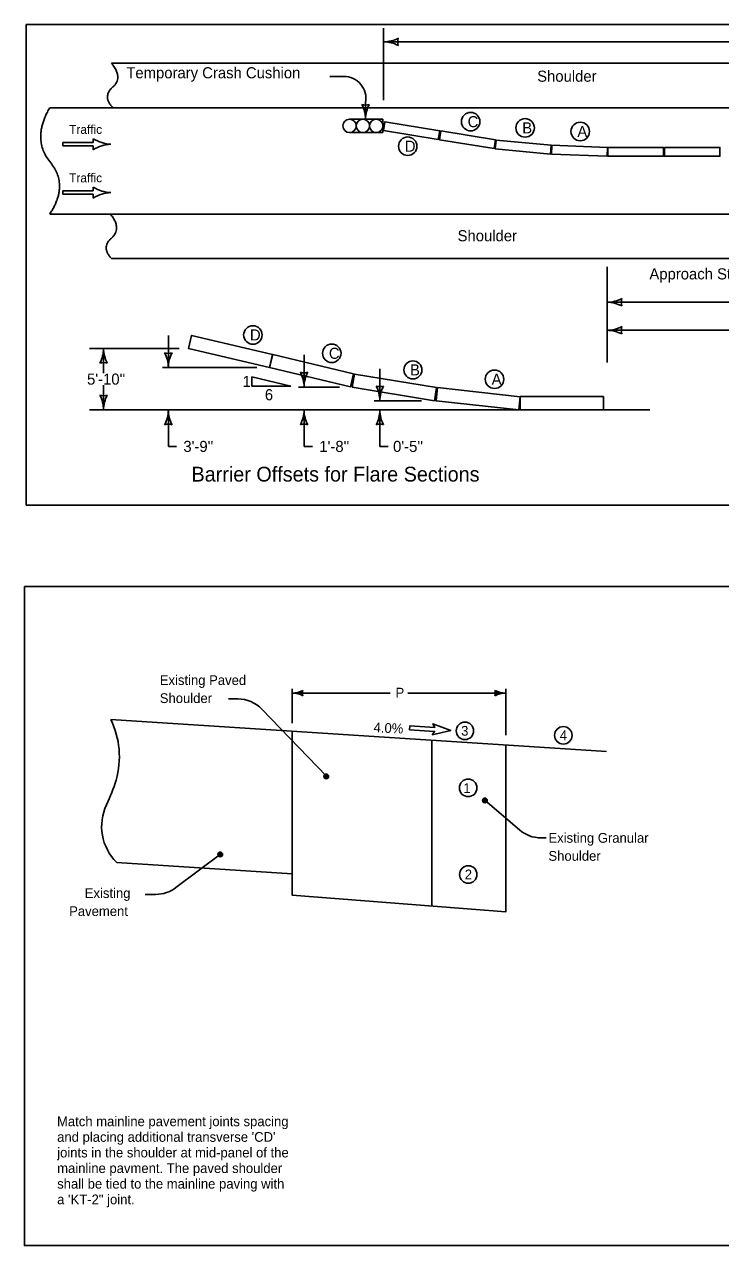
# Model space of a CAD drawing. Extents: x 8045 to 81668, y 6217 to 16762.
# Drawn here: x 8045 to 8986, y 10467 to 12118 of the extents above; entities that cross this region are included whole.
import ezdxf

# ---------------------------------------------------------------- set-up
doc = ezdxf.new("R2010")
doc.units = 0
for name, color, linetype in [('dsnNonPlotable', 7, 'Continuous'), ('dsnStdBlock', 7, 'Continuous'), ('dsnStdBlockModified', 7, 'Continuous'), ('dsnStdBorder', 7, 'Continuous'), ('dsnStdLineWork', 7, 'Continuous'), ('dsnStdNameDate', 7, 'Continuous'), ('Level 5', 7, 'Continuous')]:
    doc.layers.add(name, color=color, linetype=linetype)

msp = doc.modelspace()

# ---------------------------------------------------------------- linework, layer by layer
at = {"layer": 'dsnNonPlotable'}
for p, q in [((8530, 12113.1), (8530, 12015.6)), ((8530, 12094.5), (9408.5, 12094.5)), ((8162.3, 12065.5), (9290.8, 12065.5)), ((8476.2, 12047.8), (8457.5, 12047.8)), ((8078.7, 12005.5), (9320.8, 12005.5)), ((8505.7, 12012.4), (8505.7, 11989.9)), ((8484.1, 11989.9), (8529.1, 11989.9)), ((8529.1, 11989.9), (8529.1, 11971.9)), ((8529.1, 11971.9), (8484.1, 11971.9)), ((8527.9, 11977.6), (8529.2, 11977.3)), ((8529.7, 11973.9), (8529.7, 11973.9)), ((8137.6, 11958.3), (8096.3, 11958.3)), ((8096.3, 11958.3), (8096.3, 11953.8)), ((8137.6, 11963.6), (8137.6, 11958.3)), ((8161.5, 11956.1), (8161.5, 11956.1)), ((8096.3, 11953.8), (8137.6, 11953.8)), ((8137.6, 11953.8), (8137.6, 11948.6)), ((8137.6, 11892.9), (8096.3, 11892.9)), ((8096.3, 11892.9), (8096.3, 11888.4)), ((8137.6, 11898.1), (8137.6, 11892.9)), ((8161.5, 11890.6), (8161.5, 11890.6)), ((8096.3, 11888.4), (8137.6, 11888.4)), ((8137.6, 11888.4), (8137.6, 11883.1)), ((8078.7, 11861.5), (9320.8, 11861.5)), ((8162.3, 11801.5), (9290.8, 11801.5)), ((8832.1, 11790.2), (8832.1, 11661.1)), ((8832.1, 11742.4), (9058.2, 11742.4)), ((8239.1, 11697.6), (8239.1, 11654.1)), ((8832.1, 11704.5), (9422.9, 11704.5)), ((8253.6, 11680.1), (8132.4, 11680.1)), ((8151.5, 11680.1), (8151.5, 11646.6)), ((8422.6, 11671.2), (8422.6, 11627.7)), ((8358.5, 11654.1), (8231.3, 11654.1)), ((8525, 11652.6), (8525, 11609.1)), ((8151.5, 11630.3), (8151.5, 11596.8)), ((8470.4, 11627.7), (8414.9, 11627.7)), ((8581.3, 11609.1), (8517.2, 11609.1)), ((8889.8, 11596.8), (8132.4, 11596.8)), ((8239.1, 11596.8), (8239.1, 11547.5)), ((8422.6, 11596.8), (8422.6, 11547.5)), ((8525, 11596.8), (8525, 11569.8)), ((8525, 11569.8), (8525, 11547.5)), ((8239.1, 11547.5), (8250.2, 11547.5)), ((8422.6, 11547.5), (8433.8, 11547.5)), ((8525, 11547.5), (8536.1, 11547.5))]:
    msp.add_line(p, q, dxfattribs=at)
for points in [[(8605.9, 11974.3), (8531.9, 11986.5), (8530, 11974.6), (8604, 11962.5)], [(8681.4, 11961.9), (8607.4, 11974.1), (8605.5, 11962.2), (8679.5, 11950.1)], [(8756.8, 11954.7), (8682.2, 11961.8), (8681, 11949.9), (8755.7, 11942.8)], [(8832.6, 11951.8), (8757.7, 11954.8), (8757.2, 11942.8), (8832.1, 11939.8)], [(8833.3, 11951.8), (8908.3, 11951.8), (8908.3, 11939.8), (8833.3, 11939.8)], [(8909.8, 11951.8), (8984.8, 11951.8), (8984.8, 11939.8), (8909.8, 11939.8)], [(8379.9, 11671.7), (8270.4, 11697.6), (8266.2, 11680.1), (8375.7, 11654.2)], [(8489.6, 11645.7), (8380.2, 11671.6), (8376, 11654.1), (8485.5, 11628.2)], [(8601.7, 11627), (8490.7, 11645.4), (8487.8, 11627.7), (8598.8, 11609.2)], [(8714.8, 11614.7), (8603, 11627), (8601, 11609.1), (8712.8, 11596.8)], [(8827.3, 11614.8), (8714.8, 11614.8), (8714.8, 11596.8), (8827.3, 11596.8)]]:
    msp.add_lwpolyline(points, close=True, dxfattribs=at)
for centre, radius in [((8484.1, 11980.9), 9), ((8484.1, 11980.9), 9), ((8502.1, 11980.9), 9), ((8502.1, 11980.9), 9), ((8520.1, 11980.9), 9), ((8520.1, 11980.9), 9), ((8647.7, 11986.6), 12.5), ((8721.4, 11978.2), 12.5), ((8795.9, 11973.3), 12.5), ((8562.7, 11953.4), 12.5), ((8353.4, 11698.2), 12.5), ((8460, 11673.4), 12.5), ((8569.7, 11651), 12.2), ((8680, 11638.3), 12.5)]:
    msp.add_circle(centre, radius, dxfattribs=at)
for centre, radius, start, end in [((8530, 12137), 42.5, 270, 298.0725), ((8530, 12052), 42.5, 61.9275, 90), ((8565.6, 12094.5), 16.4, 162.2666, 197.7334), ((8476.2, 12017.8), 30, 349.6463, 90), ((8505.7, 12025.5), 16.4, 252.2666, 287.7333), ((8463.2, 11989.9), 42.5, 360, 28.0725), ((8548.2, 11989.9), 42.5, 151.9275, 180), ((8163.5, 12004.4), 48.4, 237.618, 267.648), ((8163.5, 11907.8), 48.4, 92.352, 122.382), ((8163.5, 11939), 48.4, 237.618, 267.648), ((8163.5, 11842.3), 48.4, 92.352, 122.382), ((8832.1, 11784.9), 42.5, 270, 298.0725), ((8832.1, 11699.9), 42.5, 61.9275, 90), ((8867.8, 11742.4), 16.4, 162.2666, 197.7334), ((8832.1, 11747), 42.5, 270, 298.0725), ((8867.8, 11704.5), 16.4, 162.2666, 197.7334), ((8832.1, 11662), 42.5, 61.9275, 90), ((8109, 11680.1), 42.5, 331.9275, 0), ((8194, 11680.1), 42.5, 180, 208.0725), ((8239.1, 11689.7), 16.4, 252.2666, 287.7334), ((8196.6, 11654.1), 42.5, 0, 28.0725), ((8281.6, 11654.1), 42.5, 151.9275, 180), ((8151.5, 11644.4), 16.4, 72.2666, 107.7334), ((8422.6, 11663.3), 16.4, 252.2666, 287.7334), ((8380.1, 11627.7), 42.5, 0, 28.0725), ((8465.1, 11627.7), 42.5, 151.9275, 180), ((8525, 11644.7), 16.4, 252.2666, 287.7334), ((8482.5, 11609.1), 42.5, 0, 28.0725), ((8567.5, 11609.1), 42.5, 151.9275, 180), ((8151.5, 11632.4), 16.4, 252.2666, 287.7334), ((8109, 11596.8), 42.5, 0, 28.0725), ((8194, 11596.8), 42.5, 151.9275, 180), ((8196.6, 11596.8), 42.5, 331.9275, 0), ((8281.6, 11596.8), 42.5, 180, 208.0725), ((8380.1, 11596.8), 42.5, 331.9275, 0), ((8465.1, 11596.8), 42.5, 180, 208.0725), ((8482.5, 11596.8), 42.5, 331.9275, 0), ((8567.5, 11596.8), 42.5, 180, 208.0725), ((8239.1, 11561.2), 16.4, 72.2666, 107.7334), ((8422.6, 11561.2), 16.4, 72.2666, 107.7334), ((8525, 11561.2), 16.4, 72.2666, 107.7334)]:
    msp.add_arc(centre, radius, start, end, dxfattribs=at)
for points in [[(8162.3, 12065.5), (8178.4, 12046.2), (8149.5, 12020.6), (8164, 12005.5)], [(8078.7, 12005.5), (8054.1, 11962.9), (8104.9, 11900.7), (8078.7, 11861.5)], [(8160.7, 11861.5), (8176.8, 11842.1), (8147.9, 11816.5), (8162.3, 11801.5)]]:
    msp.add_open_spline(points, degree=2, dxfattribs=at)
at = {"layer": 'dsnStdBlock'}
msp.add_line((8047, 12118.1), (8047, 12118.1), dxfattribs=at)
at = {"layer": 'dsnStdBlockModified'}
for p, q in [((8047, 12118.1), (11152, 12118.1)), ((8047, 11468.1), (8047, 12118.1))]:
    msp.add_line(p, q, dxfattribs=at)
at = {"layer": 'dsnStdBorder'}
msp.add_line((11152, 11468.1), (8047, 11468.1), dxfattribs=at)
at = {"layer": 'dsnStdLineWork'}
for p, q in [((8406.6, 11173.2), (8406.6, 11219.5)), ((8406.6, 11213.9), (8420.4, 11213.9)), ((8406.6, 11213.9), (8538.9, 11213.9)), ((8562.8, 11213.9), (8695.1, 11213.9)), ((8695.1, 11213.9), (8681.2, 11213.9)), ((8695.1, 11157.2), (8695.1, 11219.5)), ((8320.4, 11206.1), (8333.1, 11206.1)), ((8365.6, 11192.3), (8452.8, 11101.5)), ((8161.2, 11178.2), (8831.5, 11134.8)), ((8595.3, 10925.9), (8595.3, 11150.1)), ((8713.6, 11029.1), (8667.3, 11068.8)), ((8749.8, 11018.2), (8742.9, 11018.2)), ((8169.4, 10984.9), (8406.6, 10969.5)), ((8249.4, 10951.1), (8309.4, 10996.1)), ((8221.9, 10941.7), (8207.9, 10941.7))]:
    msp.add_line(p, q, dxfattribs=at)
for points in [[(8420.1, 11211.3), (8419.6, 11213.9), (8420.1, 11216.5), (8417.1, 11215), (8412.1, 11213.9), (8417.4, 11212.7), (8419.7, 11211.7), (8419.1, 11213.9), (8419.3, 11215.6), (8417.3, 11214.6), (8414.6, 11213.9), (8417.5, 11213.1), (8419, 11212.6), (8418.7, 11214.8), (8416.7, 11213.9), (8418.3, 11213.4), (8418.3, 11214.2), (8417.6, 11213.9)], [(8681.5, 11216.5), (8682, 11213.9), (8681.5, 11211.3), (8684.6, 11212.8), (8689.5, 11213.9), (8684.2, 11215.1), (8681.9, 11216.1), (8682.5, 11213.9), (8682.3, 11212.2), (8684.3, 11213.2), (8687, 11213.9), (8684.1, 11214.7), (8682.6, 11215.3), (8682.9, 11213.1), (8684.9, 11213.9), (8683.3, 11214.4), (8683.3, 11213.6), (8684, 11213.9)], [(8406.6, 11162.6), (8406.6, 10940.7), (8695.1, 10918.1), (8695.1, 11143.7)], [(8454.8, 11103.1), (8453.7, 11103.5), (8452.1, 11104.4), (8450.7, 11103.4), (8449.9, 11102.2), (8449.6, 11100.5), (8450.8, 11099.5), (8452.2, 11098.5), (8453.7, 11098.8), (8454.8, 11099.7), (8455.4, 11101.7), (8454.6, 11102.7), (8453.2, 11103.5), (8451.4, 11103.7), (8450.4, 11102.6), (8450.2, 11101), (8451.2, 11099.8), (8452.6, 11098.9), (8453.4, 11099.3), (8454.4, 11099.9), (8454.9, 11101.4), (8454, 11102.2), (8452.8, 11103.1), (8451.6, 11103.2), (8451, 11101.9), (8451.1, 11100.6), (8452.1, 11099.6), (8452.9, 11099.9), (8453.8, 11100.1), (8454.1, 11101.4), (8453.5, 11102.3), (8452.5, 11102.6), (8451.8, 11101.9), (8451.6, 11101.1), (8452.1, 11100.2), (8452.7, 11100.2), (8453.2, 11100.4), (8453.5, 11101.3), (8453.1, 11101.9), (8452.4, 11102.1), (8452.1, 11101.6), (8452.2, 11101), (8452.6, 11100.6), (8453, 11100.9), (8452.8, 11101.5)], [(8669.2, 11070.7), (8668.1, 11071.2), (8666.6, 11072), (8665.2, 11071), (8664.3, 11069.8), (8664.1, 11068.1), (8665.3, 11067.1), (8666.6, 11066.1), (8668.1, 11066.4), (8669.2, 11067.3), (8669.8, 11069.3), (8669.1, 11070.3), (8667.6, 11071.1), (8665.9, 11071.4), (8664.8, 11070.2), (8664.7, 11068.6), (8665.6, 11067.4), (8667, 11066.5), (8667.9, 11067), (8668.9, 11067.5), (8669.3, 11069), (8668.4, 11069.9), (8667.3, 11070.7), (8666, 11070.8), (8665.4, 11069.5), (8665.6, 11068.2), (8666.5, 11067.2), (8667.3, 11067.5), (8668.2, 11067.8), (8668.5, 11069), (8668, 11069.9), (8667, 11070.2), (8666.2, 11069.5), (8666, 11068.7), (8666.5, 11067.8), (8667.1, 11067.8), (8667.7, 11068), (8667.9, 11068.9), (8667.6, 11069.5), (8666.9, 11069.7), (8666.5, 11069.2), (8666.6, 11068.6), (8667.1, 11068.2), (8667.4, 11068.5), (8667.2, 11069.1)], [(8311.4, 10997.7), (8310.3, 10998.1), (8308.8, 10998.9), (8307.4, 10998), (8306.5, 10996.8), (8306.3, 10995.1), (8307.5, 10994), (8308.9, 10993), (8310.4, 10993.4), (8311.4, 10994.3), (8312, 10996.3), (8311.3, 10997.2), (8309.8, 10998.1), (8308.1, 10998.3), (8307, 10997.2), (8306.9, 10995.5), (8307.8, 10994.4), (8309.2, 10993.4), (8310.1, 10993.9), (8311.1, 10994.5), (8311.5, 10996), (8310.6, 10996.8), (8309.5, 10997.6), (8308.3, 10997.8), (8307.6, 10996.5), (8307.8, 10995.2), (8308.8, 10994.1), (8309.5, 10994.4), (8310.4, 10994.7), (8310.7, 10996), (8310.2, 10996.9), (8309.2, 10997.2), (8308.4, 10996.5), (8308.3, 10995.6), (8308.7, 10994.8), (8309.3, 10994.8), (8309.9, 10995), (8310.2, 10995.9), (8309.8, 10996.5), (8309.1, 10996.6), (8308.8, 10996.2), (8308.8, 10995.6), (8309.3, 10995.1), (8309.6, 10995.5), (8309.4, 10996.1)]]:
    msp.add_lwpolyline(points, dxfattribs=at)
msp.add_lwpolyline([(8595.8, 11157.3), (8620.8, 11163.5), (8596.7, 11172.5), (8599.3, 11167.3), (8565.5, 11169.5), (8565.2, 11164.3), (8599, 11162.2)], close=True, dxfattribs=at)
for centre, radius in [((8640, 11162.9), 11.8), ((8773, 11156.8), 11.8), ((8452.5, 11101.3), 3.15), ((8644.4, 11085.8), 11.8), ((8667, 11068.9), 3.15), ((8309.2, 10995.8), 3.15), ((8644.5, 10968.7), 11.8)]:
    msp.add_circle(centre, radius, dxfattribs=at)
for centre, radius, start, end in [((8406.6, 11244.5), 30.6, 270, 298.0725), ((8406.6, 11183.3), 30.6, 61.9275, 90), ((8432.2, 11213.9), 11.8, 162.2666, 197.7334), ((8669.4, 11213.9), 11.8, 342.2666, 17.7334), ((8695.1, 11244.5), 30.6, 241.9275, 270), ((8695.1, 11183.3), 30.6, 90, 118.0725), ((8333.1, 11161.1), 45, 43.8398, 90), ((8059.9, 11128.1), 113, 343.6708, 26.3373), ((7955.9, 11158.6), 221.4, 334.4332, 343.6708), ((8217.1, 11033.6), 68.2, 154.4332, 225.5564), ((8742.9, 11063.2), 45, 229.3882, 270), ((8221.9, 10986.7), 45, 270, 307.6187)]:
    msp.add_arc(centre, radius, start, end, dxfattribs=at)
at = {"layer": 'dsnStdNameDate'}
msp.add_lwpolyline([(8044.5, 11358.2), (9595.3, 11358.2), (9595.3, 10466.9), (8044.5, 10466.9)], close=True, dxfattribs=at)
at = {"layer": 'Level 5'}
for p, q in [((8404.7, 11629.1), (8352, 11641.6)), ((8352, 11641.6), (8352, 11629.1)), ((8352, 11629.1), (8404.7, 11629.1))]:
    msp.add_line(p, q, dxfattribs=at)

# ---------------------------------------------------------------- texts
at = {"layer": 'dsnStdLineWork'}
for s, height, p in [('Barrier Offsets for Flare Sections', 20, (8270.4, 11500)), ('Existing Paved', 13.2, (8227.5, 11224.9)), ('Shoulder', 13.2, (8227.5, 11200.5)), ('P', 13.2, (8546.2, 11207.9)), ('3', 13.2, (8634.9, 11156.3)), ('4', 13.2, (8768.2, 11150.2)), ('1', 13.2, (8637.9, 11078.9)), ('Existing Granular', 13.2, (8752.9, 11011.6)), ('Shoulder', 13.2, (8752.9, 10987.2)), ('2', 13.2, (8639.8, 10962.1)), ('Existing', 13.2, (8126.1, 10936.9)), ('Pavement', 13.2, (8105, 10912.5)), ('Match mainline pavement joints spacing ', 13.2, (8088.6, 10628.3)), ("and placing additional transverse 'CD' ", 13.2, (8088.8, 10607.2)), ('joints in the shoulder at mid-panel of the ', 13.2, (8088.8, 10586.1)), ('mainline pavment. The paved shoulder ', 13.2, (8088.8, 10565)), ('shall be tied to the mainline paving with ', 13.2, (8088.8, 10543.9)), ('a \'KT-2" joint.', 13.2, (8088.8, 10522.7))]:
    msp.add_text(s, height=height, dxfattribs=at).set_placement(p)
msp.add_text('4.0%', height=13.2, rotation=357.4961, dxfattribs=at).set_placement((8516.3, 11161))
at = {"layer": 'Level 5'}
for s, height, p in [('Temporary Crash Cushion', 15, (8182.3, 12045.2)), ('Shoulder', 15, (8737.7, 12040.6)), ('C', 15, (8643.7, 11979.1)), ('Traffic', 12, (8105, 11970.1)), ('B', 15, (8717.5, 11970.7)), ('A', 15, (8792, 11965.8)), ('D', 15, (8558.8, 11945.9)), ('Traffic', 12, (8105, 11904.6)), ('Shoulder', 15, (8630.1, 11824.9)), ("Approach Storage Area (minimum 20')", 15, (8889.4, 11773.3)), ('D', 15, (8349.4, 11690.7)), ('C', 15, (8456.1, 11665.9)), ('B', 15, (8565.8, 11643.5)), ("5'-10''", 15, (8129.2, 11631)), ('1', 15, (8339.4, 11627.9)), ('A', 15, (8676.1, 11630.8)), ('6', 15, (8369.6, 11609.9)), ("3'-9''", 15, (8259.4, 11540)), ("1'-8''", 15, (8443.2, 11540)), ("0'-5''", 15, (8542.9, 11540))]:
    msp.add_text(s, height=height, dxfattribs=at).set_placement(p)

doc.saveas('drawing.dxf')
